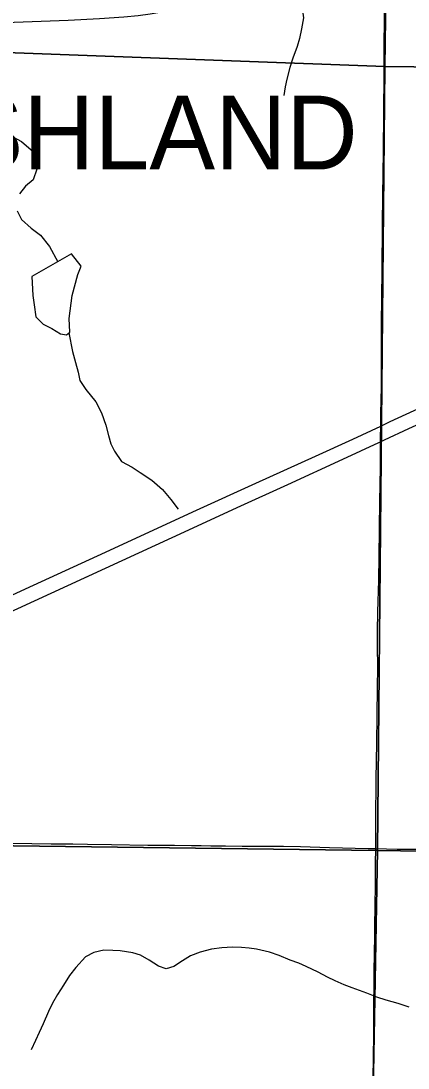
# Model space of a CAD drawing. Extents: x 1874609 to 2204689, y 815661 to 1281160.
# Drawn here: x 2021766 to 2024389, y 1028928 to 1036022 of the extents above; entities that cross this region are included whole.
import ezdxf

# ---------------------------------------------------------------- set-up
doc = ezdxf.new("R2010")
doc.units = 0
for name, color, linetype in [('GM_X_Corporation_Text', 7, 'Continuous'), ('GM_X_County_Road', 7, 'Continuous'), ('GM_X_Interstate_Route', 7, 'Continuous'), ('GM_X_Minor_Lake', 7, 'Continuous'), ('GM_X_Minor_River', 7, 'Continuous'), ('GM_X_Section', 7, 'Continuous'), ('GM_X_State_Route', 7, 'Continuous'), ('GM_X_US_Route', 7, 'Continuous')]:
    doc.layers.add(name, color=color, linetype=linetype)

msp = doc.modelspace()

# ---------------------------------------------------------------- linework, layer by layer
at = {"layer": 'GM_X_County_Road'}
for points in [[(2021609.4, 1030452.1), (2021839.2, 1030450.1), (2021970.4, 1030448.3), (2022118.1, 1030446.3), (2022216.5, 1030444.8), (2022380.5, 1030443), (2022626.6, 1030439.4), (2022708.6, 1030438.7), (2022806.9, 1030437.7), (2022921.6, 1030437), (2022987.2, 1030436.1), (2023052.8, 1030434.8), (2023151.1, 1030433), (2023265.6, 1030431.7), (2023347.6, 1030431.3), (2023544.6, 1030430.9), (2023659.5, 1030429.1), (2023856.4, 1030423.5), (2024118.7, 1030415.9), (2024170.3, 1030415.8)], [(2024170.3, 1030415.8), (2024315.3, 1030411.8), (2024446.5, 1030410.2)]]:
    msp.add_lwpolyline(points, dxfattribs=at)
at = {"layer": 'GM_X_Interstate_Route'}
for points in [[(2024191, 1033166.4), (2024202.6, 1033171.8), (2024230.3, 1033184.6), (2024393.9, 1033261.1), (2024707.9, 1033403.1), (2025871, 1033936.8), (2026169.5, 1034073.3), (2026617.3, 1034277.4), (2027109.1, 1034503.9), (2027110.1, 1034504.3)], [(2017236.4, 1029953.7), (2017761.2, 1030224.5), (2018373.8, 1030539.7), (2018548.8, 1030630), (2018767.2, 1030743.3), (2018887.3, 1030805.1), (2019015.2, 1030870.8), (2019264, 1030996.6), (2019557.9, 1031142.5), (2019794.6, 1031255.5), (2020122.1, 1031407.2), (2020525.1, 1031590.9), (2020823.6, 1031727.5), (2021032.1, 1031823.8), (2021330.2, 1031961), (2021852.1, 1032200.3), (2022284.4, 1032399), (2022955.4, 1032706.8), (2023358.1, 1032891.4), (2023761.6, 1033074.2), (2024015.6, 1033189.5), (2024203.9, 1033277.9), (2024268.1, 1033308.1), (2024730.6, 1033519.6)], [(2016222.7, 1029319.6), (2017753.6, 1030109.5), (2018584.8, 1030538.2), (2018861.6, 1030681.3), (2018886.2, 1030694.2), (2018977.9, 1030742.4), (2019271.5, 1030889.6), (2019639.6, 1031070.7), (2019935.5, 1031213), (2020889.6, 1031652.1), (2021232.9, 1031809.1), (2021516.6, 1031938.4), (2022903.5, 1032574.4), (2023231.5, 1032725.4), (2023574.9, 1032882), (2023947.7, 1033053.2), (2024191, 1033166.4)]]:
    msp.add_lwpolyline(points, dxfattribs=at)
at = {"layer": 'GM_X_Minor_Lake'}
for points in [[(2021839.8, 1034290.7), (2021847.4, 1034162.2), (2021855.3, 1034098), (2021867.1, 1034017.7), (2021917.1, 1033967.3), (2021975.2, 1033939), (2022033.2, 1033902.7), (2022075.3, 1033896.6), (2022097.5, 1033914.5), (2022093.7, 1034006.8), (2022114.2, 1034161.3), (2022150.7, 1034303.6), (2022175, 1034361.7), (2022109, 1034444.2)], [(2022109, 1034444.2), (2021839.8, 1034290.7)]]:
    msp.add_lwpolyline(points, dxfattribs=at)
at = {"layer": 'GM_X_Minor_River'}
for points in [[(2022906.7, 1036822.5), (2022976.2, 1036768.7), (2023018.2, 1036696.3), (2023052.1, 1036634), (2023088, 1036573.7), (2023136, 1036517.3), (2023198, 1036471), (2023254.1, 1036442.7), (2023328.2, 1036412.3), (2023398.4, 1036378), (2023454.4, 1036351.7), (2023526.5, 1036313.3), (2023580.6, 1036271), (2023642.6, 1036204.6), (2023670.4, 1036124.2), (2023680.2, 1036043.9), (2023668, 1035967.7), (2023653.7, 1035903.5), (2023637.5, 1035849.4), (2023609.2, 1035769.3), (2023589, 1035707.1), (2023566.7, 1035627), (2023556.5, 1035574.8), (2023548.3, 1035516.7)], [(2021706.1, 1035240.2), (2021770.2, 1035205.8), (2021836.2, 1035149.4), (2021866.1, 1035085.1), (2021874, 1035018.9), (2021847.7, 1034946.7), (2021797.4, 1034902.8), (2021757.1, 1034850.8)], [(2021740.8, 1034736.4), (2021768.7, 1034676.1), (2021834.7, 1034617.7), (2021898.8, 1034571.3), (2021958.7, 1034492.9), (2022015.2, 1034390.7)], [(2022091.3, 1033909.6), (2022115.1, 1033782), (2022135, 1033707.8), (2022152.8, 1033643.5), (2022164.7, 1033587.2), (2022206.7, 1033524.9), (2022272.6, 1033442.4), (2022312.5, 1033368), (2022340.4, 1033283.7), (2022358.2, 1033213.4), (2022374.1, 1033157.1), (2022400, 1033106.9), (2022448, 1033038.5), (2022520.1, 1033000.1), (2022574.1, 1032963.8), (2022652.2, 1032911.4), (2022724.2, 1032848.9), (2022782.2, 1032780.5), (2022832.1, 1032714.1)], [(2024396, 1029341.6), (2024321.9, 1029366), (2024241.8, 1029388.4), (2024177.7, 1029408.8), (2024109.7, 1029435.2), (2024009.6, 1029471.7), (2023955.5, 1029492), (2023895.5, 1029520.4), (2023843.4, 1029544.7), (2023779.4, 1029579.1), (2023699.4, 1029617.5), (2023649.3, 1029639.8), (2023589.3, 1029658.2), (2023515.2, 1029690.6), (2023449.1, 1029713), (2023363, 1029733.4), (2023312.9, 1029741.6), (2023260.8, 1029745.9), (2023198.7, 1029748.2), (2023126.5, 1029742.5), (2023058.3, 1029732.8), (2022980, 1029713), (2022915.8, 1029689.2), (2022859.6, 1029655.4), (2022801.3, 1029615.5), (2022749.1, 1029599.7), (2022699, 1029618), (2022635, 1029658.4), (2022577, 1029692.8), (2022525, 1029709), (2022438.8, 1029721.5), (2022388.7, 1029723.7), (2022326.6, 1029726), (2022260.4, 1029710.2), (2022204.1, 1029682.4), (2022137.7, 1029610.5), (2022095.4, 1029554.5), (2022055.1, 1029490.5), (2022012.8, 1029426.5), (2021980.5, 1029368.4), (2021952.2, 1029312.4), (2021915.8, 1029228.3), (2021889.6, 1029170.2), (2021865.3, 1029114.2), (2021835, 1029052.1)]]:
    msp.add_lwpolyline(points, dxfattribs=at)
at = {"layer": 'GM_X_Section'}
for points in [[(2018988, 1041097.3), (2024307, 1041050.6), (2024232.1, 1035713.6), (2018912.9, 1035910.5)], [(2024307, 1041050.6), (2029613.9, 1041007.7), (2029549.1, 1035652.8), (2024232.1, 1035713.6)], [(2018912.9, 1035910.5), (2024232.1, 1035713.6), (2024181.3, 1030402.7), (2018892.4, 1030469.7)], [(2024232.1, 1035713.6), (2029549.1, 1035652.8), (2029474.2, 1030325.8), (2024181.3, 1030402.7)], [(2024181.3, 1030402.7), (2024088.3, 1025127.9), (2019652, 1025148.6), (2018801.5, 1025176.8), (2018892.4, 1030469.7)], [(2029474.2, 1030325.8), (2029401.2, 1025034.9), (2025080.9, 1025087.9), (2024088.3, 1025127.9), (2024181.3, 1030402.7)]]:
    msp.add_lwpolyline(points, close=True, dxfattribs=at)
at = {"layer": 'GM_X_State_Route'}
for points in [[(2024210, 1033970.2), (2024212, 1034151.4), (2024213.3, 1034331.9), (2024216.4, 1034643.4), (2024218.8, 1034840.3), (2024222, 1035135.7), (2024226.3, 1035661.1), (2024228, 1035873.7), (2024232.5, 1036146.2)], [(2024202, 1033077.6), (2024202.6, 1033171.8), (2024202.8, 1033199.4), (2024203.9, 1033277.9), (2024205, 1033363.7), (2024208.1, 1033544.2), (2024209.8, 1033741), (2024209.6, 1033938.1), (2024210, 1033970.2)], [(2024200.1, 1032876.8), (2024201.5, 1033002.4), (2024202, 1033077.6)], [(2024170.3, 1030415.8), (2024170.2, 1030458.8), (2024171, 1030606.5), (2024173.9, 1030885.5), (2024178.5, 1031131.7), (2024180.8, 1031312.2), (2024182.8, 1031509.2), (2024184.5, 1031640.4), (2024182.3, 1031788.1), (2024181.6, 1031886.7), (2024184.7, 1032018.1), (2024191.7, 1032231.1), (2024193.5, 1032395.1), (2024195.4, 1032575.8), (2024198.9, 1032772.7), (2024200.1, 1032876.8)], [(2024120.6, 1027095.9), (2024122.6, 1027166.6), (2024130.4, 1027527.5), (2024135.9, 1027765.8), (2024136.1, 1027773.6), (2024139.6, 1028003.2), (2024145.6, 1028282.1), (2024148.8, 1028511.7), (2024150.4, 1028610.1), (2024151.1, 1028708.5), (2024156.1, 1029150.7), (2024157.2, 1029265.5), (2024158.2, 1029380.3), (2024159.4, 1029478.7), (2024160.5, 1029560.6), (2024162.7, 1029724), (2024163.4, 1029805.8), (2024163.9, 1029887.8), (2024169, 1030166.7), (2024168.3, 1030314.3), (2024170.3, 1030415.8)]]:
    msp.add_lwpolyline(points, dxfattribs=at)
at = {"layer": 'GM_X_US_Route'}
msp.add_lwpolyline([(2021596.4, 1036009.9), (2022085.5, 1036027.1), (2022298.6, 1036039.1), (2022462.4, 1036050), (2022560.6, 1036059.6), (2022642, 1036070.7), (2022771.6, 1036092.6), (2022916.7, 1036120.8), (2023012.9, 1036142.7), (2023124.1, 1036172), (2023250.3, 1036208.5), (2023344.2, 1036238.6), (2023452.5, 1036277.3), (2023544.4, 1036313.1), (2023650.1, 1036358.5), (2023739.3, 1036400.4), (2023914.8, 1036490), (2024016.1, 1036544.4), (2024162.5, 1036631)], dxfattribs=at)

# ---------------------------------------------------------------- texts
at = {"layer": 'GM_X_Corporation_Text'}
msp.add_text('ASHLAND', height=500, rotation=0.00001, dxfattribs=at).set_placement((2020889.3, 1035015.9))

doc.saveas('drawing.dxf')
